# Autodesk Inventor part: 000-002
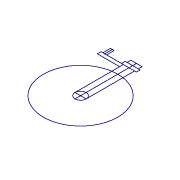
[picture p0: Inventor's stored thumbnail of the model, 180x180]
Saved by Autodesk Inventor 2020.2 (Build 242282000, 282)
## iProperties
Created: 2015-05
Part Number: 000-002
Material: Ogólny
Document SubType Name: Modeling
Designer: F.Stasiak
Density: 1 g/cm^3
Appearance: Domyślna
Manager: www.cadconsulting.pl
Company: Fabian Stasiak CAD Consulting
Author: F.Stasiak
Subject: Zbiór ćwiczeń. Autodesk Inventor 2020. Kurs podstawowy
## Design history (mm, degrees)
node "Bloki"
  sketch "Koło"
    geometry: L1 (-30.505, 0)-(-30.505, 260); L2 (-40.505, 280)-(39.495, 280); L3 (39.495, 280)-(39.495, 260); L4 (39.495, 260)-(-40.505, 260); L5 (-40.505, 260)-(-40.505, 280); L6 (29.495, 260)-(29.495, 0); L7 (-30.505, 280)-(-30.505, 300); L8 (-30.505, 300)-(29.495, 300); L9 (29.495, 300)-(29.495, 280); L10 (-30.505, 260)-(-150.505, 260); L11 (-150.505, 260)-(-150.505, 240); L12 (-150.505, 240)-(-30.505, 240); L13 (-30.505, 240)-(-30.505, 260); L14 (-140.505, 260)-(-120.505, 260); L15 (-120.505, 260)-(-120.505, 300); L16 (-120.505, 300)-(-140.505, 300); L17 (-140.505, 300)-(-140.505, 260); L18 (-0.505, 303)-(-0.505, -33); L19 (-130.505, 303)-(-130.505, 257); L20 (-33.505, 0)-(32.495, 0); C1 r 200 at (-0.505, 0); A1 r 30 centre (-0.505, 0) between (-30.505, 0) and (29.495, 0); 1 further point
    constraints: 40 end point, 10 point on line, 2 centre point, 2 point on circle
sketch "Szkic1"
  geometry: 2 further points
  constraints: 1 coincident, 1 other
  node "Koło:1"
